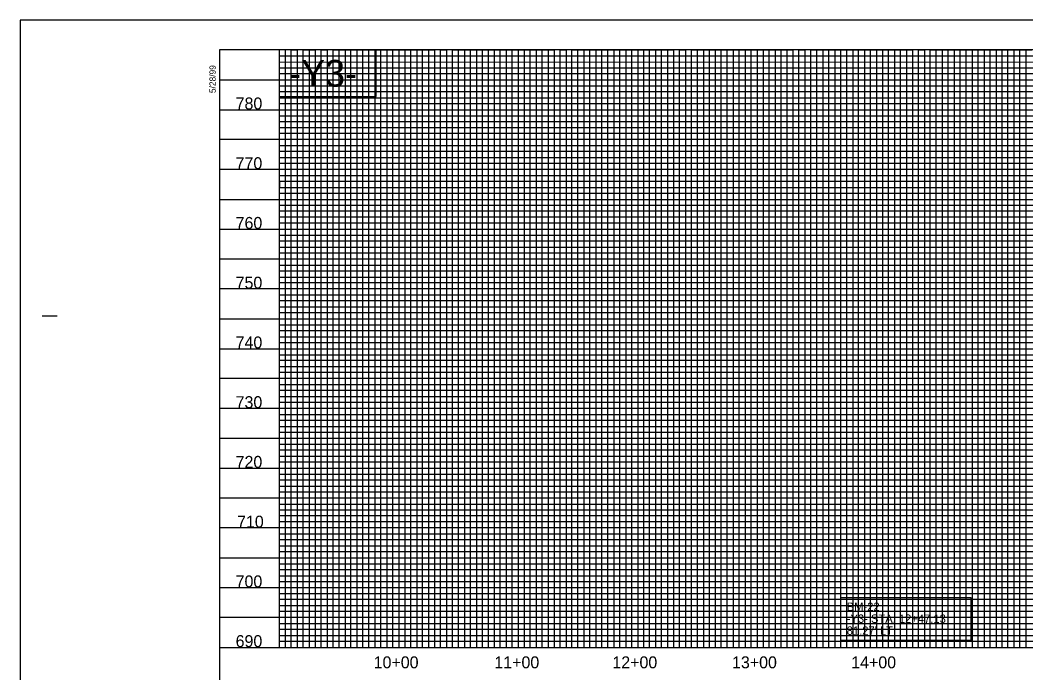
# Model space of a CAD drawing. Extents: x 1524869 to 1526553, y 501099 to 502199.
# Drawn here: x 1524869 to 1525711, y 501652 to 502199 of the extents above; entities that cross this region are included whole.
import ezdxf

# ---------------------------------------------------------------- set-up
doc = ezdxf.new("R2010")
doc.units = 0
for name, color, linetype in [('Exist Vertical Profile Horizontal Axis Label Major', 7, 'Continuous'), ('Exist Vertical Profile Vertical Axis Label', 7, 'Continuous'), ('Prop Grid Mask', 7, 'Continuous'), ('Prop Horizontal Alignment Curve and Spiral Data', 7, 'Continuous'), ('Prop Vertical Profile Curve Label', 7, 'Continuous'), ('Prop VPI Label', 7, 'Continuous'), ('Sheet Layout Profile Border Port 1', 7, 'Continuous'), ('Sheet Plot Border Outside CELL', 7, 'Continuous'), ('Sheet Profile CELL', 7, 'Continuous'), ('Sheet Profile Grid Major CELL', 7, 'Continuous'), ('Sheet Profile Grid Middle CELL', 7, 'Continuous'), ('Sheet Profile Grid Minor CELL', 7, 'Continuous')]:
    doc.layers.add(name, color=color, linetype=linetype)

msp = doc.modelspace()

# ---------------------------------------------------------------- linework, layer by layer
at = {"layer": 'Prop Grid Mask'}
for points in [[(1525086.08, 502134.52), (1525167.19, 502134.52), (1525167.19, 502173.56), (1525086.08, 502173.56)], [(1525556.08, 501715.26), (1525665.13, 501715.26), (1525665.13, 501679.25), (1525556.08, 501679.25)]]:
    msp.add_lwpolyline(points, close=True, dxfattribs=at)
at = {"layer": 'Sheet Layout Profile Border Port 1'}
msp.add_lwpolyline([(1525086.08, 501673.56), (1525636.08, 501673.56), (1525636.08, 502173.56), (1525086.08, 502173.56)], close=True, dxfattribs=at)
at = {"layer": 'Sheet Plot Border Outside CELL'}
msp.add_lwpolyline([(1524869.08, 501098.56), (1526553.08, 501098.56), (1526553.08, 502198.56), (1524869.08, 502198.56)], close=True, dxfattribs=at)
at = {"layer": 'Sheet Profile CELL'}
for p, q in [((1524887.58, 501951.06), (1524900.08, 501951.06)), ((1525036.08, 501673.56), (1526536.08, 501673.56))]:
    msp.add_line(p, q, dxfattribs=at)
msp.add_lwpolyline([(1526536.08, 502173.56), (1525036.08, 502173.56), (1525036.08, 501123.56), (1526536.08, 501123.56)], close=True, dxfattribs=at)
at = {"layer": 'Sheet Profile Grid Major CELL'}
for points in [[(1525086.08, 502173.56), (1525086.08, 501673.56), (1525136.08, 501673.56), (1525136.08, 502173.56), (1525186.08, 502173.56), (1525186.08, 501673.56), (1525236.08, 501673.56), (1525236.08, 502173.56), (1525286.08, 502173.56), (1525286.08, 501673.56), (1525336.08, 501673.56), (1525336.08, 502173.56), (1525386.08, 502173.56), (1525386.08, 501673.56), (1525436.08, 501673.56), (1525436.08, 502173.56), (1525486.08, 502173.56), (1525486.08, 501673.56), (1525536.08, 501673.56), (1525536.08, 502173.56), (1525586.08, 502173.56), (1525586.08, 501673.56), (1525636.08, 501673.56), (1525636.08, 502173.56), (1525686.08, 502173.56), (1525686.08, 501673.56), (1525736.08, 501673.56)], [(1525036.08, 502123.56), (1526336.08, 502123.56)], [(1526336.08, 502073.56), (1525036.08, 502073.56), (1525036.08, 502023.56), (1526336.08, 502023.56)], [(1526536.08, 501973.56), (1525036.08, 501973.56), (1525036.08, 501923.56), (1526536.08, 501923.56)], [(1526536.08, 501873.56), (1525036.08, 501873.56), (1525036.08, 501823.56), (1526536.08, 501823.56)], [(1526536.08, 501773.56), (1525036.08, 501773.56), (1525036.08, 501773.56), (1525036.08, 501723.56), (1526536.08, 501723.56)]]:
    msp.add_lwpolyline(points, dxfattribs=at)
at = {"layer": 'Sheet Profile Grid Middle CELL'}
msp.add_line((1525036.08, 502148.56), (1526336.03, 502148.56), dxfattribs=at)
for points in [[(1525111.08, 502173.56), (1525111.08, 501673.56), (1525161.08, 501673.56), (1525161.08, 502173.56), (1525211.08, 502173.56), (1525211.08, 501673.56), (1525261.08, 501673.56), (1525261.08, 502173.56), (1525311.08, 502173.56), (1525311.08, 501673.56), (1525361.08, 501673.56), (1525361.08, 502173.56), (1525411.08, 502173.56), (1525411.08, 501673.56), (1525461.08, 501673.56), (1525461.08, 502173.56), (1525511.08, 502173.56), (1525511.08, 501673.56), (1525561.08, 501673.56), (1525561.08, 502173.56), (1525611.08, 502173.56), (1525611.08, 501673.56), (1525661.08, 501673.56), (1525661.08, 501673.56), (1525661.08, 502173.56), (1525711.08, 502173.56), (1525711.08, 501673.56), (1525761.08, 501673.56)], [(1526336.08, 502098.56), (1525036.08, 502098.56), (1525036.08, 502048.56), (1526336.08, 502048.56)], [(1526536.08, 501998.56), (1525036.08, 501998.56), (1525036.08, 501948.56), (1526361.08, 501948.56)], [(1526536.08, 501898.56), (1525036.08, 501898.56), (1525036.08, 501848.56), (1526536.08, 501848.56)], [(1526536.08, 501798.56), (1525036.08, 501798.56), (1525036.08, 501748.56), (1526536.08, 501748.56)], [(1526536.08, 501698.56), (1525036.08, 501698.56)]]:
    msp.add_lwpolyline(points, dxfattribs=at)
at = {"layer": 'Sheet Profile Grid Minor CELL'}
for p, q in [((1525086.08, 502168.56), (1525936.08, 502168.56)), ((1525936.08, 502163.45), (1525086.08, 502163.21)), ((1525086.08, 502158.56), (1525936.08, 502158.56)), ((1525936.08, 502038.56), (1525086.08, 502038.56)), ((1525936.08, 502033.56), (1525086.08, 502033.56)), ((1525936.08, 502028.56), (1525086.08, 502028.56)), ((1525086.08, 502018.56), (1525936.08, 502018.56)), ((1525936.08, 502013.56), (1525086.08, 502013.56)), ((1525086.08, 502008.56), (1525936.08, 502008.56)), ((1525936.08, 501988.56), (1525086.08, 501988.56)), ((1525086.08, 501983.56), (1525936.08, 501983.56)), ((1525936.08, 501963.56), (1525086.08, 501963.56)), ((1525086.08, 501958.56), (1525936.08, 501958.56)), ((1525936.08, 501938.56), (1525086.08, 501938.56)), ((1525086.08, 501933.56), (1525936.08, 501933.56)), ((1525936.08, 501928.56), (1525086.08, 501928.56)), ((1525086.08, 501918.56), (1525936.08, 501918.56)), ((1525936.08, 501913.56), (1525086.08, 501913.56)), ((1525086.08, 501908.56), (1525936.08, 501908.56)), ((1525936.08, 501903.56), (1525086.08, 501903.56)), ((1525086.08, 501893.56), (1525936.08, 501893.56)), ((1525936.08, 501888.56), (1525086.08, 501888.56)), ((1525086.08, 501883.56), (1525936.08, 501883.56)), ((1525936.08, 501878.56), (1525086.08, 501878.56)), ((1525086.08, 501868.56), (1525936.08, 501868.56)), ((1525936.08, 501863.56), (1525086.08, 501863.56)), ((1525086.08, 501858.56), (1525936.08, 501858.56)), ((1525936.08, 501853.56), (1525086.08, 501853.56)), ((1525086.08, 501843.56), (1525936.08, 501843.56)), ((1525936.08, 501838.56), (1525086.08, 501838.56)), ((1525086.08, 501833.56), (1525936.08, 501833.56)), ((1525936.08, 501828.56), (1525086.08, 501828.56)), ((1525086.08, 501818.56), (1525936.08, 501818.56)), ((1525936.08, 501813.56), (1525086.08, 501813.56)), ((1525086.08, 501808.56), (1525936.08, 501808.56)), ((1525936.08, 501803.56), (1525086.08, 501803.56)), ((1525086.08, 501793.56), (1525936.08, 501793.56)), ((1525936.08, 501788.56), (1525086.08, 501788.56)), ((1525936.08, 501783.56), (1525086.08, 501783.56)), ((1525936.08, 501778.56), (1525086.08, 501778.56)), ((1525086.08, 501768.56), (1525936.08, 501768.56)), ((1525936.08, 501763.56), (1525086.08, 501763.56)), ((1525086.08, 501758.56), (1525936.08, 501758.56)), ((1525936.08, 501753.56), (1525086.08, 501753.56)), ((1525086.08, 501743.56), (1525936.08, 501743.56)), ((1525936.08, 501738.56), (1525086.08, 501738.56)), ((1525086.08, 501733.56), (1525936.08, 501733.56)), ((1525936.08, 501728.56), (1525086.08, 501728.56)), ((1525086.08, 501718.56), (1525936.08, 501718.56)), ((1525936.08, 501713.56), (1525086.08, 501713.56)), ((1525086.08, 501708.56), (1525936.08, 501708.56)), ((1525936.08, 501703.56), (1525086.08, 501703.56)), ((1525086.08, 501693.56), (1525936.08, 501693.56)), ((1525936.08, 501688.56), (1525086.08, 501688.56)), ((1525086.08, 501683.56), (1525936.08, 501683.56))]:
    msp.add_line(p, q, dxfattribs=at)
for points in [[(1525091.08, 502173.56), (1525091.08, 501673.56), (1525096.08, 501673.56), (1525096.08, 502173.56), (1525101.08, 502173.56), (1525101.08, 501673.56), (1525106.08, 501673.56), (1525106.08, 502173.56), (1525116.08, 502173.56), (1525116.08, 501673.56), (1525121.08, 501673.56), (1525121.08, 502173.56), (1525126.08, 502173.56), (1525126.08, 501673.56), (1525131.08, 501673.56), (1525141.08, 501673.56), (1525146.08, 501673.56), (1525146.08, 502173.56), (1525151.08, 502173.56), (1525151.08, 501673.56), (1525156.08, 501673.56), (1525156.08, 502173.56), (1525166.08, 502173.56), (1525166.08, 501673.56), (1525171.08, 501673.56), (1525171.08, 502173.56), (1525176.08, 502173.56), (1525176.08, 501673.56), (1525181.08, 501673.56), (1525181.08, 502173.56), (1525191.08, 502173.56), (1525191.08, 501673.56), (1525196.08, 501673.56), (1525196.08, 502173.56), (1525201.08, 502173.56), (1525201.08, 501673.56), (1525206.08, 501673.56), (1525206.08, 502173.56), (1525216.08, 502173.56), (1525216.08, 501673.56), (1525221.08, 501673.56), (1525221.08, 502173.56), (1525226.08, 502173.56), (1525226.08, 501673.56), (1525231.08, 501673.56), (1525231.08, 502173.56), (1525241.08, 502173.56), (1525241.08, 501673.56), (1525246.08, 501673.56), (1525246.08, 502173.56), (1525251.08, 502173.56), (1525251.08, 501673.56), (1525256.08, 501673.56), (1525256.08, 502173.56), (1525266.08, 502173.56), (1525266.08, 501673.56), (1525271.08, 501673.56), (1525271.08, 502173.56), (1525276.08, 502173.56), (1525276.08, 501673.56), (1525281.08, 501673.56), (1525281.08, 502173.56), (1525291.08, 502173.56), (1525291.08, 501673.56), (1525296.08, 501673.56), (1525296.08, 502173.56), (1525301.08, 502173.56), (1525301.08, 501673.56)], [(1525131.08, 501673.56), (1525131.08, 502173.56), (1525141.08, 502173.56), (1525141.08, 501673.56)], [(1525301.08, 501673.56), (1525306.08, 501673.56), (1525306.08, 502173.56), (1525316.08, 502173.56), (1525316.08, 501673.56), (1525321.08, 501673.56), (1525321.08, 502173.56), (1525326.08, 502173.56), (1525326.08, 501673.56), (1525331.08, 501673.56), (1525331.08, 502173.56), (1525341.08, 502173.56), (1525341.08, 501673.56), (1525346.08, 501673.56), (1525346.08, 502173.56), (1525351.08, 502173.56), (1525351.08, 501673.56), (1525356.08, 501673.56), (1525356.08, 502173.56), (1525366.08, 502173.56), (1525366.08, 501673.56), (1525371.08, 501673.56), (1525371.08, 502173.56), (1525376.08, 502173.56), (1525376.08, 501673.56), (1525381.08, 501673.56), (1525381.08, 502173.56), (1525391.08, 502173.56), (1525391.08, 501673.56), (1525396.08, 501673.56), (1525396.08, 502173.56), (1525401.08, 502173.56), (1525401.08, 501673.56), (1525406.08, 501673.56), (1525406.08, 502173.56), (1525416.08, 502173.56), (1525416.08, 501673.56), (1525421.08, 501673.56), (1525421.08, 502173.56), (1525426.08, 502173.56), (1525426.08, 501673.56), (1525431.08, 501673.56), (1525431.08, 502173.56), (1525441.08, 502173.56), (1525441.08, 501673.56), (1525446.08, 501673.56), (1525446.08, 502173.56), (1525451.08, 502173.56), (1525451.08, 501673.56), (1525456.08, 501673.56), (1525456.08, 502173.56), (1525466.08, 502173.56), (1525466.08, 501673.56), (1525471.08, 501673.56), (1525471.08, 502173.56), (1525476.08, 502173.56), (1525476.08, 501673.56), (1525481.08, 501673.56), (1525481.08, 502173.56), (1525491.08, 502173.56), (1525491.08, 501673.56), (1525496.08, 501673.56), (1525496.08, 502173.56), (1525501.08, 502173.56), (1525501.08, 501673.56), (1525506.08, 501673.56), (1525506.08, 502173.56), (1525516.08, 502173.56), (1525516.08, 501673.56), (1525521.08, 501673.56), (1525521.08, 502173.56), (1525526.08, 502173.56), (1525526.08, 501673.56), (1525531.08, 501673.56), (1525531.08, 502173.56), (1525541.08, 502173.56), (1525541.08, 501673.56), (1525546.08, 501673.56), (1525546.08, 502173.56), (1525551.08, 502173.56), (1525551.08, 501673.56), (1525556.08, 501673.56), (1525556.08, 502173.56), (1525566.08, 502173.56), (1525566.08, 501673.56), (1525571.08, 501673.56), (1525571.08, 502173.56), (1525576.08, 502173.56), (1525576.08, 501673.56), (1525581.08, 501673.56), (1525581.08, 502173.56), (1525591.08, 502173.56), (1525591.08, 501673.56), (1525596.08, 501673.56), (1525596.08, 502173.56), (1525601.08, 502173.56), (1525601.08, 501673.56), (1525606.08, 501673.56), (1525606.08, 502173.56), (1525616.08, 502173.56)], [(1525616.08, 502173.56), (1525616.08, 501673.56), (1525621.08, 501673.56), (1525621.08, 502173.56), (1525626.08, 502173.56), (1525626.08, 501673.56), (1525631.08, 501673.56), (1525631.08, 502173.56), (1525641.08, 502173.56), (1525641.08, 501673.56), (1525646.08, 501673.56), (1525646.08, 502173.56), (1525651.08, 502173.56), (1525651.08, 501673.56), (1525656.08, 501673.56), (1525656.08, 502173.56), (1525666.08, 502173.56), (1525666.08, 501673.56), (1525671.08, 501673.56), (1525671.08, 502173.56), (1525676.08, 502173.56), (1525676.08, 501673.56), (1525681.08, 501673.56), (1525681.08, 502173.56), (1525691.08, 502173.56), (1525691.08, 501673.56), (1525696.08, 501673.56), (1525696.08, 502173.56), (1525701.08, 502173.56), (1525701.08, 501673.56), (1525706.08, 501673.56), (1525706.08, 502173.56), (1525716.08, 502173.56)], [(1525936.08, 502153.56), (1525086.08, 502153.56), (1525086.08, 502143.56), (1525936.08, 502143.56)], [(1525936.08, 502138.56), (1525086.08, 502138.56), (1525086.08, 502133.56), (1525936.08, 502133.56)], [(1525936.08, 502128.56), (1525086.08, 502128.56), (1525086.08, 502118.56), (1525936.08, 502118.56)], [(1525936.08, 502113.56), (1525086.08, 502113.56), (1525086.08, 502108.56), (1525936.08, 502108.56)], [(1525936.08, 502103.56), (1525086.08, 502103.56), (1525086.08, 502093.56), (1525936.08, 502093.56)], [(1525936.08, 502088.56), (1525086.08, 502088.56), (1525086.08, 502083.56), (1525936.08, 502083.56)], [(1525936.08, 502078.56), (1525086.08, 502078.56), (1525086.08, 502068.56), (1525936.08, 502068.56)], [(1525936.08, 502063.46), (1525086.18, 502063.46), (1525086.18, 502058.56), (1525936.08, 502058.56)], [(1525936.08, 502053.56), (1525086.08, 502053.56), (1525086.08, 502043.56), (1525936.08, 502043.56)], [(1525936.08, 502003.56), (1525086.08, 502003.56), (1525086.08, 501993.56), (1525936.08, 501993.56)], [(1525936.08, 501978.56), (1525086.08, 501978.56), (1525086.08, 501968.56), (1525936.08, 501968.56)], [(1525936.08, 501953.56), (1525086.08, 501953.56), (1525086.08, 501943.56), (1525936.08, 501943.56)], [(1525936.08, 501678.56), (1525086.08, 501678.56)]]:
    msp.add_lwpolyline(points, dxfattribs=at)

# ---------------------------------------------------------------- texts
at = {"layer": 'Exist Vertical Profile Horizontal Axis Label Major'}
for s, p in [('10+00', (1525165.07, 501656.06)), ('11+00', (1525266.13, 501656.06)), ('12+00', (1525364.91, 501656.06)), ('13+00', (1525465.07, 501656.06)), ('14+00', (1525564.86, 501656.06))]:
    msp.add_text(s, height=10, dxfattribs=at).set_placement(p)
at = {"layer": 'Exist Vertical Profile Vertical Axis Label'}
for s, p in [('780', (1525049.51, 502123.81)), ('770', (1525049.51, 502073.81)), ('760', (1525049.51, 502023.81)), ('750', (1525049.51, 501973.81)), ('740', (1525049.51, 501923.81)), ('730', (1525049.51, 501873.81)), ('720', (1525049.51, 501823.81)), ('710', (1525050.71, 501773.81)), ('700', (1525049.51, 501723.81)), ('690', (1525049.51, 501673.81))]:
    msp.add_text(s, height=10, dxfattribs=at).set_placement(p)
at = {"layer": 'Prop Horizontal Alignment Curve and Spiral Data'}
msp.add_text('-Y3-', height=22.5, rotation=360, dxfattribs=at).set_placement((1525094.28, 502142.79))
at = {"layer": 'Prop Vertical Profile Curve Label'}
msp.add_text("81.27' LT", height=7, dxfattribs=at).set_placement((1525561.09, 501684.1))
at = {"layer": 'Prop VPI Label'}
for s, p in [('BM-22', (1525561.09, 501704.1)), ('-Y3- STA. 12+47.13', (1525561.09, 501694.1))]:
    msp.add_text(s, height=7, dxfattribs=at).set_placement(p)
at = {"layer": 'Sheet Profile CELL'}
msp.add_text('5/28/99', height=5.25, rotation=90, dxfattribs=at).set_placement((1525032.84, 502137.47))

doc.saveas('drawing.dxf')
